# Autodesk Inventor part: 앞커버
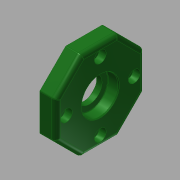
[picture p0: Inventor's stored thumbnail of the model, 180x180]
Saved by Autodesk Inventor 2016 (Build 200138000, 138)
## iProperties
Created: 2015-11
Part Number: 앞커버
Material: 알루미늄 6061
Document SubType Name: Modeling
Designer: mduedu
Density: 1 g/cm^3
Appearance: 매끄러움 - 짙은 산림 녹색
Author: mduedu
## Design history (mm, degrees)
sketch "스케치5" dims "d66" = 60
  geometry: L1 (12.426, 30)-(30, 12.426); L2 (30, 12.426)-(30, -12.426); L3 (30, -12.426)-(12.426, -30); L4 (12.426, -30)-(-12.426, -30); L5 (-12.426, -30)-(-30, -12.426); L6 (-30, -12.426)-(-30, 12.426); L7 (-30, 12.426)-(-12.426, 30); L8 (-12.426, 30)-(12.426, 30); 4 further points
  constraints: 16 end point, 2 coincident, 2 vertical alignment, 1 midpoint, 19 other
extrude "돌출2" new body sketch "스케치5" distance "d67" = 11; taper "d68" = 0 deg
sketch "스케치6"
  geometry: C1 r 16 at (0, 0); 1 further point
  constraints: 1 centre point, 1 coincident
  dimensions: "d69" = 32 diameter of C1
extrude "돌출3" join sketch "스케치6" distance "d70" = 3; taper "d71" = 0 deg
hole "구멍7" diameter "d98" = 25; stored, may be unused: countersink angle "d102" = 90 deg, drill point angle "d104" = 0 deg; dims "d96" = 10, "d97" = 10, "d99" = 6, "d100" = 4, "d101" = 2, "d103" = 3
hole "구멍8" diameter "d107" = 25; stored, may be unused: countersink angle "d111" = 90 deg, drill point angle "d113" = 0 deg; dims "d108" = 6, "d109" = 4, "d110" = 2, "d112" = 7.3, "d143" = 10, "d144" = 10
hole "구멍9" diameter "d116" = 17; stored, may be unused: countersink angle "d120" = 90 deg, drill point angle "d122" = 0 deg; dims "d114" = 10, "d115" = 10, "d117" = 6, "d118" = 4, "d119" = 2, "d121" = 7.7
chamfer "모따기2" distance "d123" = 0.7; stored, may be unused: second distance "d124" = 2, angle "d125" = 30 deg
fillet "모깎기11" dims "d126" = 0.3
fillet "모깎기12" dims "d127" = 1
fillet "모깎기13" dims "d128" = 3
fillet "모깎기14" dims "d129" = 3
fillet "모깎기15" dims "d130" = 0.3
sketch "스케치8" dims "d131" = 46
  geometry: 3 further points
  constraints: 2 vertical alignment, 1 coincident, 2 other
hole "구멍10" sketch "스케치8" at (0, 23) diameter "d132" = 4.5; stored, may be unused: countersink angle "d136" = 90 deg, drill point angle "d138" = 0 deg; dims "d133" = 6, "d134" = 8, "d135" = 4.6, "d137" = 7.7
node "솔리드2"
pattern_circular "원형 패턴4" dims angle "d140" = 360 deg
